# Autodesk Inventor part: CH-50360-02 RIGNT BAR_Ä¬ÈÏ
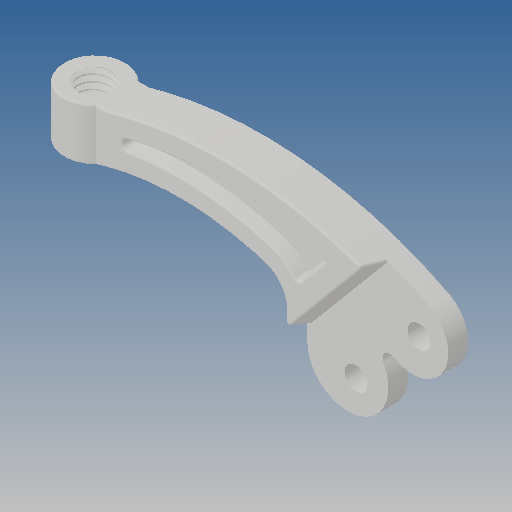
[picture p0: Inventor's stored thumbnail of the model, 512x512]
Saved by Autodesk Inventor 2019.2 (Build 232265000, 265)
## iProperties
Created: 2010-06
Part Number: CH-50360-02 RIGNT BAR_Ä¬ÈÏ
Material: Ogólny
Document SubType Name: Modeling
Designer: CADENGINEERING4
Density: 1 g/cm^3
Appearance: Domyślna
Author: CADENGINEERING4
Revision Number: ÈÎºÎ
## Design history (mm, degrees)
feature "NONE"
node "Bryła1"
